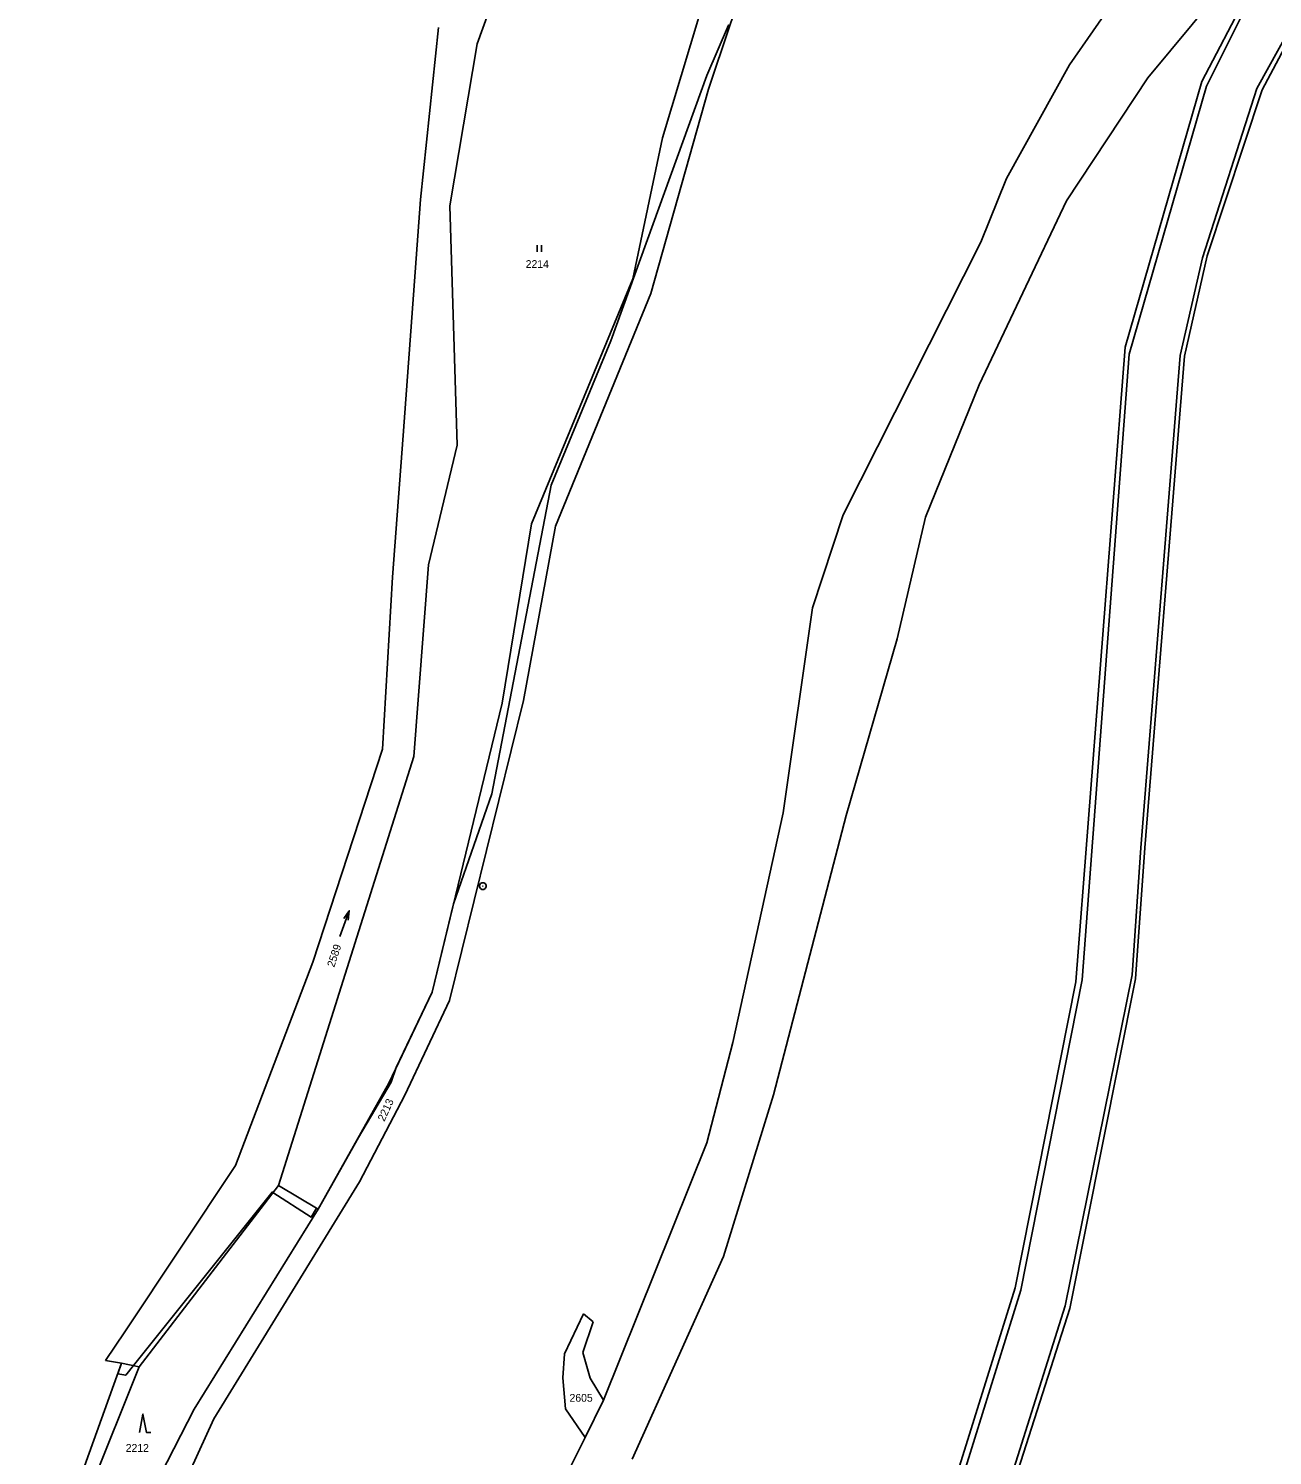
# Model space of a CAD drawing. Extents: x -806774 to -803680, y -1151731 to -1150053.
# Drawn here: x -806614.7 to -806342.9, y -1151124.5 to -1150812.7 of the extents above; entities that cross this region are included whole.
import ezdxf

# ---------------------------------------------------------------- set-up
doc = ezdxf.new("R2010")
doc.units = 0
for name, color, linetype in [('1', 7, 'Continuous'), ('11', 7, 'Continuous'), ('2', 7, 'Continuous'), ('3', 7, 'Continuous'), ('4', 7, 'Continuous'), ('8', 7, 'Continuous')]:
    doc.layers.add(name, color=color, linetype=linetype)

msp = doc.modelspace()

# ---------------------------------------------------------------- linework, layer by layer
at = {"layer": '1'}
for p, q in [((-806516.7, -1150816.08), (-806492.53, -1150749.14)), ((-806365.52, -1150789.31), (-806387.27, -1150820.63)), ((-806358.34, -1150824.28), (-806344.65, -1150798)), ((-806370.14, -1150823.51), (-806352.38, -1150802.05)), ((-806468.06, -1150809.49), (-806476.18, -1150836.62)), ((-806529.06, -1150850.09), (-806525.14, -1150812.53)), ((-806466.17, -1150825.98), (-806461.53, -1150812.09)), ((-806522.7, -1150851.47), (-806516.7, -1150816.08)), ((-806345.15, -1150826.11), (-806338.48, -1150813.51)), ((-806387.27, -1150820.63), (-806401.02, -1150845.49)), ((-806387.91, -1150850.42), (-806370.14, -1150823.51)), ((-806375.14, -1150882.34), (-806358.34, -1150824.28)), ((-806478.73, -1150870.6), (-806466.17, -1150825.98)), ((-806357.22, -1150862.43), (-806345.15, -1150826.11)), ((-806476.18, -1150836.62), (-806482.68, -1150867.46)), ((-806401.02, -1150845.49), (-806406.63, -1150859.45)), ((-806532.89, -1150901.68), (-806529.06, -1150850.09)), ((-806407.04, -1150890.62), (-806387.91, -1150850.42)), ((-806521.06, -1150903.81), (-806522.7, -1150851.47)), ((-806406.63, -1150859.45), (-806436.73, -1150919.01)), ((-806362.13, -1150884.33), (-806357.22, -1150862.43)), ((-806482.68, -1150867.46), (-806504.84, -1150920.96)), ((-806499.61, -1150921.48), (-806478.73, -1150870.6)), ((-806385.88, -1151021.02), (-806375.14, -1150882.34)), ((-806370.8, -1150991.76), (-806362.13, -1150884.33)), ((-806418.76, -1150919.52), (-806407.04, -1150890.62)), ((-806535.18, -1150932.62), (-806532.89, -1150901.68)), ((-806527.31, -1150929.92), (-806521.06, -1150903.81)), ((-806436.73, -1150919.01), (-806443.45, -1150939.35)), ((-806504.84, -1150920.96), (-806511.23, -1150960.17)), ((-806506.6, -1150959.54), (-806499.61, -1150921.48)), ((-806424.93, -1150946.11), (-806418.76, -1150919.52)), ((-806530.51, -1150971.79), (-806527.31, -1150929.92)), ((-806537.36, -1150970.19), (-806535.18, -1150932.62)), ((-806443.45, -1150939.35), (-806449.84, -1150984.09)), ((-806436.11, -1150984.68), (-806424.93, -1150946.11)), ((-806522.72, -1151025.1), (-806506.6, -1150959.54)), ((-806511.23, -1150960.17), (-806526.57, -1151023.31)), ((-806560.14, -1151065.55), (-806530.51, -1150971.79)), ((-806552.6, -1151016.74), (-806537.36, -1150970.19)), ((-806449.84, -1150984.09), (-806460.86, -1151034.28)), ((-806451.94, -1151045.73), (-806436.11, -1150984.68)), ((-806372.89, -1151020.38), (-806370.8, -1150991.76)), ((-806569.49, -1151061.19), (-806552.6, -1151016.74)), ((-806399.13, -1151087.92), (-806385.88, -1151021.02)), ((-806387.22, -1151092.44), (-806372.89, -1151020.38)), ((-806526.57, -1151023.31), (-806535.99, -1151043.19)), ((-806532.49, -1151045.78), (-806522.72, -1151025.1)), ((-806460.86, -1151034.28), (-806466.55, -1151056.22)), ((-806535.99, -1151043.19), (-806551.43, -1151070.69)), ((-806542.45, -1151064.75), (-806532.49, -1151045.78)), ((-806462.86, -1151081.06), (-806451.94, -1151045.73)), ((-806466.55, -1151056.22), (-806489.08, -1151112.47)), ((-806593.72, -1151097.49), (-806569.49, -1151061.19)), ((-806590.53, -1151105.18), (-806560.14, -1151065.55)), ((-806574.21, -1151116.5), (-806542.45, -1151064.75)), ((-806560.14, -1151065.55), (-806551.43, -1151070.69)), ((-806551.43, -1151070.69), (-806578.53, -1151114.39)), ((-806482.86, -1151125.33), (-806462.86, -1151081.06)), ((-806426.85, -1151176.65), (-806399.13, -1151087.92)), ((-806497.61, -1151102.34), (-806493.48, -1151093.6)), ((-806493.48, -1151093.6), (-806491.35, -1151095.33)), ((-806414.88, -1151178.55), (-806387.22, -1151092.44)), ((-806491.35, -1151095.33), (-806493.61, -1151102.03)), ((-806597.92, -1151103.78), (-806593.72, -1151097.49)), ((-806497.97, -1151107.57), (-806497.61, -1151102.34)), ((-806493.61, -1151102.03), (-806492.01, -1151107.67)), ((-806614.73, -1151165.53), (-806590.53, -1151105.18)), ((-806594.42, -1151104.37), (-806609.22, -1151145.61)), ((-806597.92, -1151103.78), (-806594.42, -1151104.37)), ((-806590.53, -1151105.18), (-806594.42, -1151104.37)), ((-806497.43, -1151114.33), (-806497.97, -1151107.57)), ((-806492.01, -1151107.67), (-806489.08, -1151112.47)), ((-806578.53, -1151114.39), (-806585.93, -1151128.77)), ((-806493.12, -1151120.59), (-806497.43, -1151114.33)), ((-806489.08, -1151112.47), (-806493.12, -1151120.59)), ((-806596.74, -1151165.66), (-806574.21, -1151116.5)), ((-806493.12, -1151120.59), (-806506.25, -1151146.99))]:
    msp.add_line(p, q, dxfattribs=at)
at = {"layer": '11'}
for points in [[(-806595.25, -1151106.68), (-806593.5, -1151107), (-806591.83, -1151104.91), (-806561.5, -1151067), (-806561.33, -1151067.11), (-806553, -1151072.5), (-806551.8, -1151070.47), (-806551.43, -1151070.69), (-806542.66, -1151055.07), (-806535.5, -1151043), (-806534.38, -1151039.79), (-806526.57, -1151023.31), (-806521.87, -1151003.98), (-806513.5, -1150980), (-806500.5, -1150912.5), (-806487.5, -1150881), (-806466.5, -1150823), (-806461.78, -1150811.99), (-806461.53, -1150812.09), (-806460.18, -1150808.26), (-806440.03, -1150761.24), (-806415.5, -1150704)], [(-806595.25, -1151106.68), (-806594.42, -1151104.37), (-806597.92, -1151103.78)]]:
    msp.add_lwpolyline(points, dxfattribs=at)
at = {"layer": '3'}
for p, q in [((-806503.62, -1150860.04), (-806503.62, -1150861.54)), ((-806502.62, -1150861.54), (-806502.62, -1150860.04)), ((-806546.74, -1151011.13), (-806544.66, -1151005.51))]:
    msp.add_line(p, q, dxfattribs=at)
for points in [[(-806545.82, -1151007.21), (-806544.66, -1151005.51), (-806544.88, -1151007.56)], [(-806590.48, -1151119.5), (-806589.73, -1151115.5), (-806588.98, -1151119.5), (-806587.98, -1151119.5)]]:
    msp.add_lwpolyline(points, dxfattribs=at)
at = {"layer": '4'}
for p, q in [((-806344.11, -1150798.77), (-806357.36, -1150825.3)), ((-806346.33, -1150825.84), (-806339.23, -1150812.92)), ((-806357.36, -1150825.3), (-806374.24, -1150883.89)), ((-806358.25, -1150862.85), (-806346.33, -1150825.84)), ((-806363.07, -1150884.18), (-806358.25, -1150862.85)), ((-806374.24, -1150883.89), (-806384.48, -1151020.64)), ((-806371.72, -1150991.74), (-806363.07, -1150884.18)), ((-806373.56, -1151019.52), (-806371.72, -1150991.74)), ((-806384.48, -1151020.64), (-806397.9, -1151088.41)), ((-806388.26, -1151091.88), (-806373.56, -1151019.52)), ((-806397.9, -1151088.41), (-806434.09, -1151204.41)), ((-806406.37, -1151149.26), (-806388.26, -1151091.88))]:
    msp.add_line(p, q, dxfattribs=at)
at = {"layer": '8'}
msp.add_line((-806515.52, -1151000.11), (-806515.42, -1151000.11), dxfattribs=at)
msp.add_lwpolyline([(-806515.28, -1150999.39), (-806514.94, -1150999.58), (-806514.75, -1150999.92), (-806514.75, -1151000.31), (-806514.94, -1151000.65), (-806515.28, -1151000.84), (-806515.67, -1151000.84), (-806516.01, -1151000.65), (-806516.2, -1151000.31), (-806516.2, -1150999.92), (-806516.01, -1150999.58), (-806515.67, -1150999.39)], close=True, dxfattribs=at)

# ---------------------------------------------------------------- texts
at = {"layer": '2'}
for s, p in [('2214', (-806506.1, -1150865.05)), ('2605', (-806496.52, -1151112.8)), ('2212', (-806593.49, -1151123.75))]:
    msp.add_text(s, height=1.7, dxfattribs=at).set_placement(p)
for s, rotation, p in [('2589', 71.7343, (-806547.94, -1151017.98)), ('2213', 65.3172, (-806536.99, -1151051.68))]:
    msp.add_text(s, height=1.7, rotation=rotation, dxfattribs=at).set_placement(p)

doc.saveas('drawing.dxf')
